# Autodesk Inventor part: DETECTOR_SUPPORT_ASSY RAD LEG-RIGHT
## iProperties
Shininess: 64.0
Length Units: 11272
Angle Units: 11279
Time Units: 11290
Mass Units: 11286
Length Display Precision: 3
Angle Display Precision: 2
Compacted: True
Part Number: DETECTOR_SUPPORT_ASSY RAD LEG-RIGHT
Document SubType Name: Modeling
Created: 2004-08
Designer: John Blackburn
Material: ALUMINUM
Manufacturer: Standard
Standards Organization: Custom
Density: 0.0
Volumn: 0.0
Area: 0.0
PropertySet Name: Model Information
Control State: 0
Master: False
Checked Out: False
Author: John Blackburn
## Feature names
1. ExtrusionBlind1
2. AM_HOLE_SI0029_1 [Hole]
3. Hole1
4. Hole2
5. AM_HOLE_SI0029_2 [Hole]
6. Hole3
7. Hole4
